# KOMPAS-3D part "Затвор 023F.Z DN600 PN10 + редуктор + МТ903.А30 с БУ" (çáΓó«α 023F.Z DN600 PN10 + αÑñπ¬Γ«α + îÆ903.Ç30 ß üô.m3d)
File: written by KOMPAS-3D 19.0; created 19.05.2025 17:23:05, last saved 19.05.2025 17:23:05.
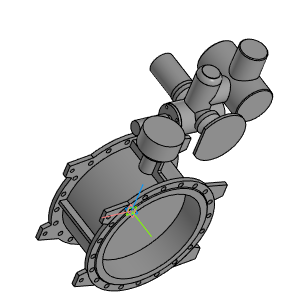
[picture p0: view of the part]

Document properties: Полное имя файла: Затвор 023F.Z DN600 PN10 + редуктор + МТ903.А30 с БУ.a3d

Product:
- Part/product: Затвор 023F.Z DN600 PN10 + редуктор + МТ903.А30 с БУ
    Масса: 682.18

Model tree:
1. Операция без истории:1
